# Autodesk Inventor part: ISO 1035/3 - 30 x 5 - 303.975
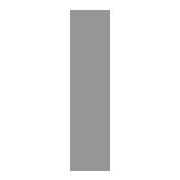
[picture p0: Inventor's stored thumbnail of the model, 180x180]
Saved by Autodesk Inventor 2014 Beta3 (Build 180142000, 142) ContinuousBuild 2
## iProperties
_CCFamilyMember: 18
_CCFamilyDisplayName: ISO 1035/3 - 1980 - Hot-rolled steel bars - Part 3: flat bars
_FrameMemberDoc: Frame Member File
_Version: 15.0.0
_GetPNFromCC: 1
Created: 2010-11
Part Number: ISO 1035/3 - 30 x 5 - 303.975
Material: Steel, Mild
Description: Hot-rolled steel bars - Part 3: flat bars
Document SubType Name: Modeling
Standard: ISO
Designer: Beta-8540w
Standard Revision: First edition 1980-11-01
Standards Organization: ISO
Language: en-US
Size Designation: 30x 5
Categories: <MemberInstance><Categories><Category DisplayName="Structural Shapes" InternalName="089c4875-fa83-4c05-b084-43b9cc11f5ed" Mnemonic="GRDR"><CategoryParameter Dis
Stock Number: 30x 5
Density: 7.86 g/cm^3
Appearance: Steel
IsCustomPart: 1
G_L: 303.975 mm
G_W: 5.000 mm
G_H: 30.000 mm
Author: Beta-8540w
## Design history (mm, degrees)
node "Start plane"
node "End plane"
node "Driven Length"
  sketch "Sketch3"
    geometry: L1 (0, 0)-(10, 0) reference
    constraints: 2 end point, 1 horizontal
  workplane "Work Plane3"
  sketch "Sketch4"
    geometry: L1 (-2, 0)-(12, 0) reference; L2 (-2, 303.975)-(12, 303.975) reference
    dimensions: "d9" = 303.9749 distance between parallel lines of L1 L2 (derived)
sketch "Sweep Path"
  geometry: L1 through (40, 30) direction (1, 0); L2 through (-20, 135) direction (1, -0); L3 through (-20, 165) direction (1, 0); L4 through (40, 270) direction (1, 0); 14 other entities
  constraints: 20 horizontal
node "Orientation Work Plane"
feature "Body" dims "d10" = 0
body "Solid1"
sketch "Sketch"
  geometry: L1 (2.5, -15)-(-2.5, -15); L2 (-2.5, -15)-(-2.5, 15); L3 (-2.5, 15)-(2.5, 15); L4 (2.5, 15)-(2.5, -15); L5 (-6, 0)-(8, 0); L6 (0, -30)-(0, 40); L7 (0, 54)-(0, -44); L8 (-9.2, 0)-(13.2, 0)
  constraints: 16 end point, 2 collinear, 2 parallel, 1 horizontal, 1 perpendicular
  dimensions: "d0" = 30 distance between parallel lines of L3 L1 (= G_W); "d1" = 5 distance between parallel lines of L4 L2 (= G_H); "d4" = 2.5 distance between parallel lines of L6 L4 (= 0.5 x d1); "d5" = 15 distance between parallel lines of L5 L3 (= 0.5 x d0)
other parameters: "G_W" = 30 [user parameter; used in 1 equation term], "G_H" = 5 [user parameter; used in 1 equation term], "G_L" = 303.9749 (= d9) [user parameter], "G_OFFSET_START" = 0 [user parameter; used in 1 equation term], "G_OFFSET_END" = 0 [user parameter; used in 1 equation term], "d6" = 0 (computed from G_OFFSET_START), "d7" = 303.9749 (= G_OFFSET_END + B_L), "B_L" = 303.9749 [user parameter; used in 1 equation term], "d8" = 90 deg
